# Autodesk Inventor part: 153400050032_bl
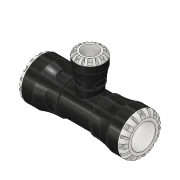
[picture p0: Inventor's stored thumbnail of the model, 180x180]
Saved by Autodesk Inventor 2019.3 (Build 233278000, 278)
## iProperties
Created: 2016-12
Part Number: 153400050032_bl
Material: PVC-Piping
Description: PLASSON G-PLASS  REDUCING TEE 50X32X50
Document SubType Name: Modeling
Designer: KIM
Mass: 664.223 g
Surface Area: 733.008 cm^2
Volume: 474.445 cm^3
Density: 1.4 g/cm^3
Appearance: Black Cast
Author: KIM
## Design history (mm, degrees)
derived "153400.ipt"
feature "Solid1::153400.ipt" dims "ScaleForDerivedMember" = 10
tag "TaggingFeature1"
body "Solid1"
other parameters: "E_" = 85 [user parameter], "l_" = 82 [user parameter], "H_" = 223 [user parameter], "d_1" = 32 [user parameter], "E_1" = 58 [user parameter], "l_1" = 56 [user parameter], "d9" = 11.25 [user parameter], "d11" = 85 [user parameter], "d12" = 62.5 [user parameter], "d230" = 58 [user parameter], "d232" = 9 [user parameter], "d1" = 34.44 [user parameter], "d3" = 62.5 [user parameter], "d4" = 85 [user parameter], "d8" = 72.25 [user parameter], "d13" = 9 [user parameter], "d14" = 9 [user parameter], "d15" = 0 [user parameter], "d17" = 360 deg [user parameter], "d19" = 8 deg [user parameter], "d20" = 1 [user parameter], "d21" = 1 [user parameter], "d22" = 8 deg [user parameter], "d24" = 0 [user parameter], "d26" = 360 deg [user parameter], "d33" = 8.5 [user parameter], "d43" = 66.3 [user parameter], "d51" = 0.85 [user parameter], "d54" = 17.5 [user parameter], "d55" = 11 [user parameter], "d57" = 17.64 [user parameter], "d58" = 0 [user parameter], "d74" = 0 [user parameter], "d77" = 4.16667 [user parameter], "d78" = 82 [user parameter], "d79" = 66.3 [user parameter], "d80" = 223 [user parameter], "d82" = 1 [user parameter], "d115" = 360 deg [user parameter], "d139" = 9 [user parameter], "d140" = 0 [user parameter], "d142" = 360 deg [user parameter], "d207" = 90 deg [user parameter], "d209" = 23.52 [user parameter], "d210" = 32 [user parameter], "d212" = 58 [user parameter], "d213" = 49.3 [user parameter], "d215" = 45.24 [user parameter], "d216" = 2.66667 [user parameter], "d217" = 56 [user parameter], "d226" = 56 [user parameter], "d228" = 14.875 [user parameter], "d229" = 7.2 [user parameter], "d233" = 7.2 [user parameter], "d234" = 0 [user parameter], "d236" = 360 deg [user parameter], "d238" = 8 deg [user parameter], "d239" = 8 deg [user parameter], "d240" = 1 [user parameter], "d241" = 1 [user parameter], "d243" = 0 [user parameter], "d245" = 360 deg [user parameter], "d247" = 1.7 [user parameter], "d248" = 4.92 [user parameter], "d249" = 3.36 [user parameter], "d250" = 9.52 [user parameter], "d252" = 11.2 [user parameter], "d253" = 7.36 [user parameter], "d254" = 17.64 [user parameter], "d255" = 0 [user parameter], "d257" = 360 deg [user parameter], "d259" = 1 [user parameter], "d261" = 0 [user parameter], "d262" = 1.7 [user parameter], "d264" = 0 [user parameter], "d266" = 0 [user parameter], "d267" = 0.85 [user parameter]
